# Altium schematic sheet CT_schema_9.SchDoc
size 297 x 239 mm
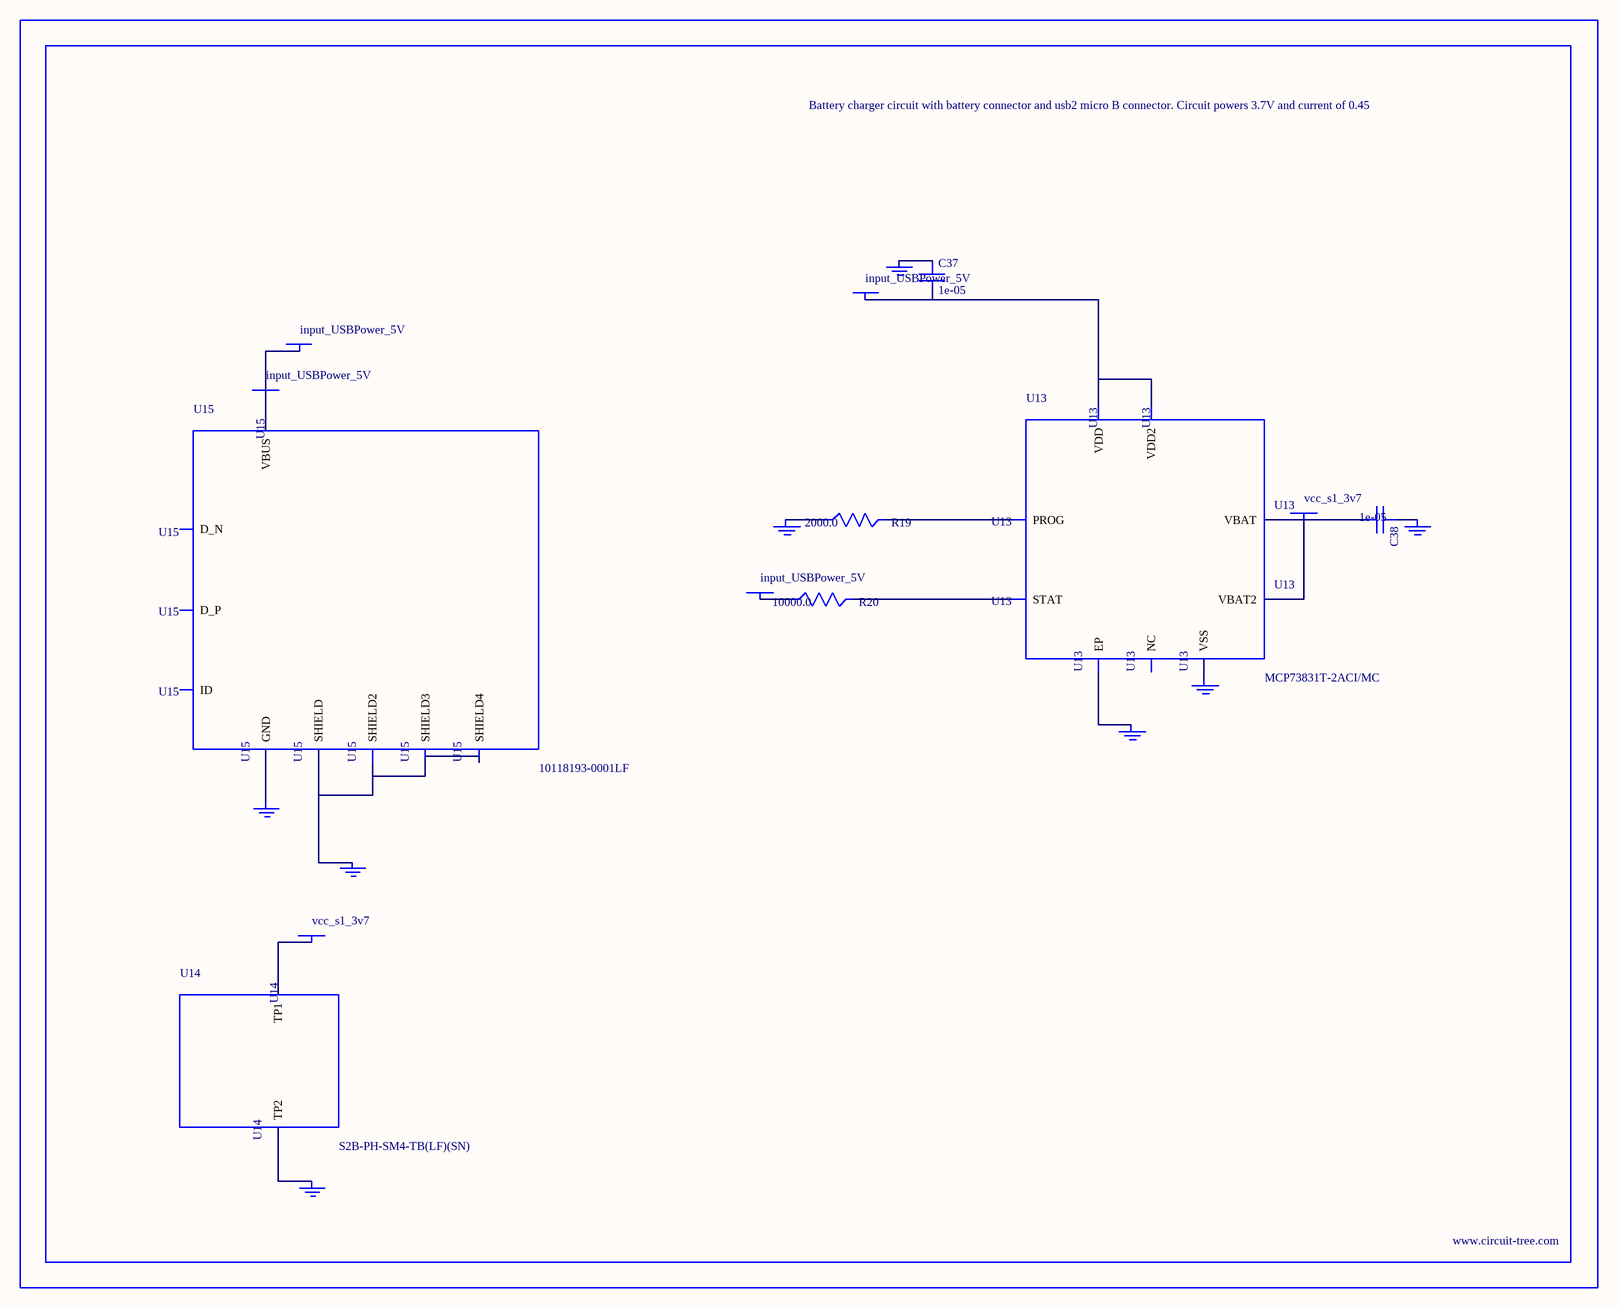
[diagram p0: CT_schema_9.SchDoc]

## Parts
BORDER8  (no value)
C37  1e-05  [C1206]
C38  1e-05  [C1206]
GND_INSTANCE_8_0  (no value)
GND_INSTANCE_8_1  (no value)
GND_INSTANCE_8_2  (no value)
GND_INSTANCE_8_3  (no value)
GND_INSTANCE_8_4  (no value)
GND_INSTANCE_8_5  (no value)
GND_INSTANCE_8_6  (no value)
GND_INSTANCE_8_7  (no value)
POWER_INSTANCE_8_0  input_USBPower_5V
POWER_INSTANCE_8_1  input_USBPower_5V
POWER_INSTANCE_8_2  vcc_s1_3v7
POWER_INSTANCE_8_3  vcc_s1_3v7
POWER_INSTANCE_8_4  input_USBPower_5V
POWER_INSTANCE_8_5  input_USBPower_5V
R19  2000.0  [R0603]
R20  10000.0  [R0603]
U13  MCP73831T-2ACI/MC  [DFN8_2X3MC]
U14  S2B-PH-SM4-TB(LF)(SN)  [JST-2-SMD]
U15  10118193-0001LF  [FCI_10118193-0001LF]

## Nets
NetC37_1: C37.1 GND_INSTANCE_8_0.0(GND)
NetC37_2: C37.2 POWER_INSTANCE_8_0.0(PWR) U13.1(VDD) U13.2(VDD2)
NetC38_1: C38.1 GND_INSTANCE_8_1.0(GND)
NetC38_2: C38.2 POWER_INSTANCE_8_2.0(PWR) U13.3(VBAT) U13.4(VBAT2)
NetGND_INSTANCE_8_2_0: GND_INSTANCE_8_2.0(GND) R19.1
NetGND_INSTANCE_8_3_0: GND_INSTANCE_8_3.0(GND) U13.9(EP)
NetGND_INSTANCE_8_4_0: GND_INSTANCE_8_4.0(GND) U13.6(VSS)
NetGND_INSTANCE_8_5_0: GND_INSTANCE_8_5.0(GND) U14.2(TP2)
NetGND_INSTANCE_8_6_0: GND_INSTANCE_8_6.0(GND) U15.6(SHIELD) U15.7(SHIELD2) U15.8(SHIELD3) U15.9(SHIELD4)
NetGND_INSTANCE_8_7_0: GND_INSTANCE_8_7.0(GND) U15.5(GND)
NetPOWER_INSTANCE_8_1_0: POWER_INSTANCE_8_1.0(PWR) R20.1
NetPOWER_INSTANCE_8_3_0: POWER_INSTANCE_8_3.0(PWR) U14.1(TP1)
NetPOWER_INSTANCE_8_4_0: POWER_INSTANCE_8_4.0(PWR) POWER_INSTANCE_8_5.0(PWR) U15.1(VBUS)
NetR19_2: R19.2 U13.8(PROG)
NetR20_2: R20.2 U13.5(STAT)

Not connected (* = marked no-connect by the designer): U13 7(NC); U15 2(D_N) 3(D_P) 4(ID)

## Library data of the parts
BORDER8 = BORDER_PAGE8
C37 C38 = C1206C106K3RACTU
GND_INSTANCE_8_0-GND_INSTANCE_8_7 = GND
POWER_INSTANCE_8_0-POWER_INSTANCE_8_5 = PWR
R19 = RC0603JR-072KL
R20 = RC0603JR-0710KL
